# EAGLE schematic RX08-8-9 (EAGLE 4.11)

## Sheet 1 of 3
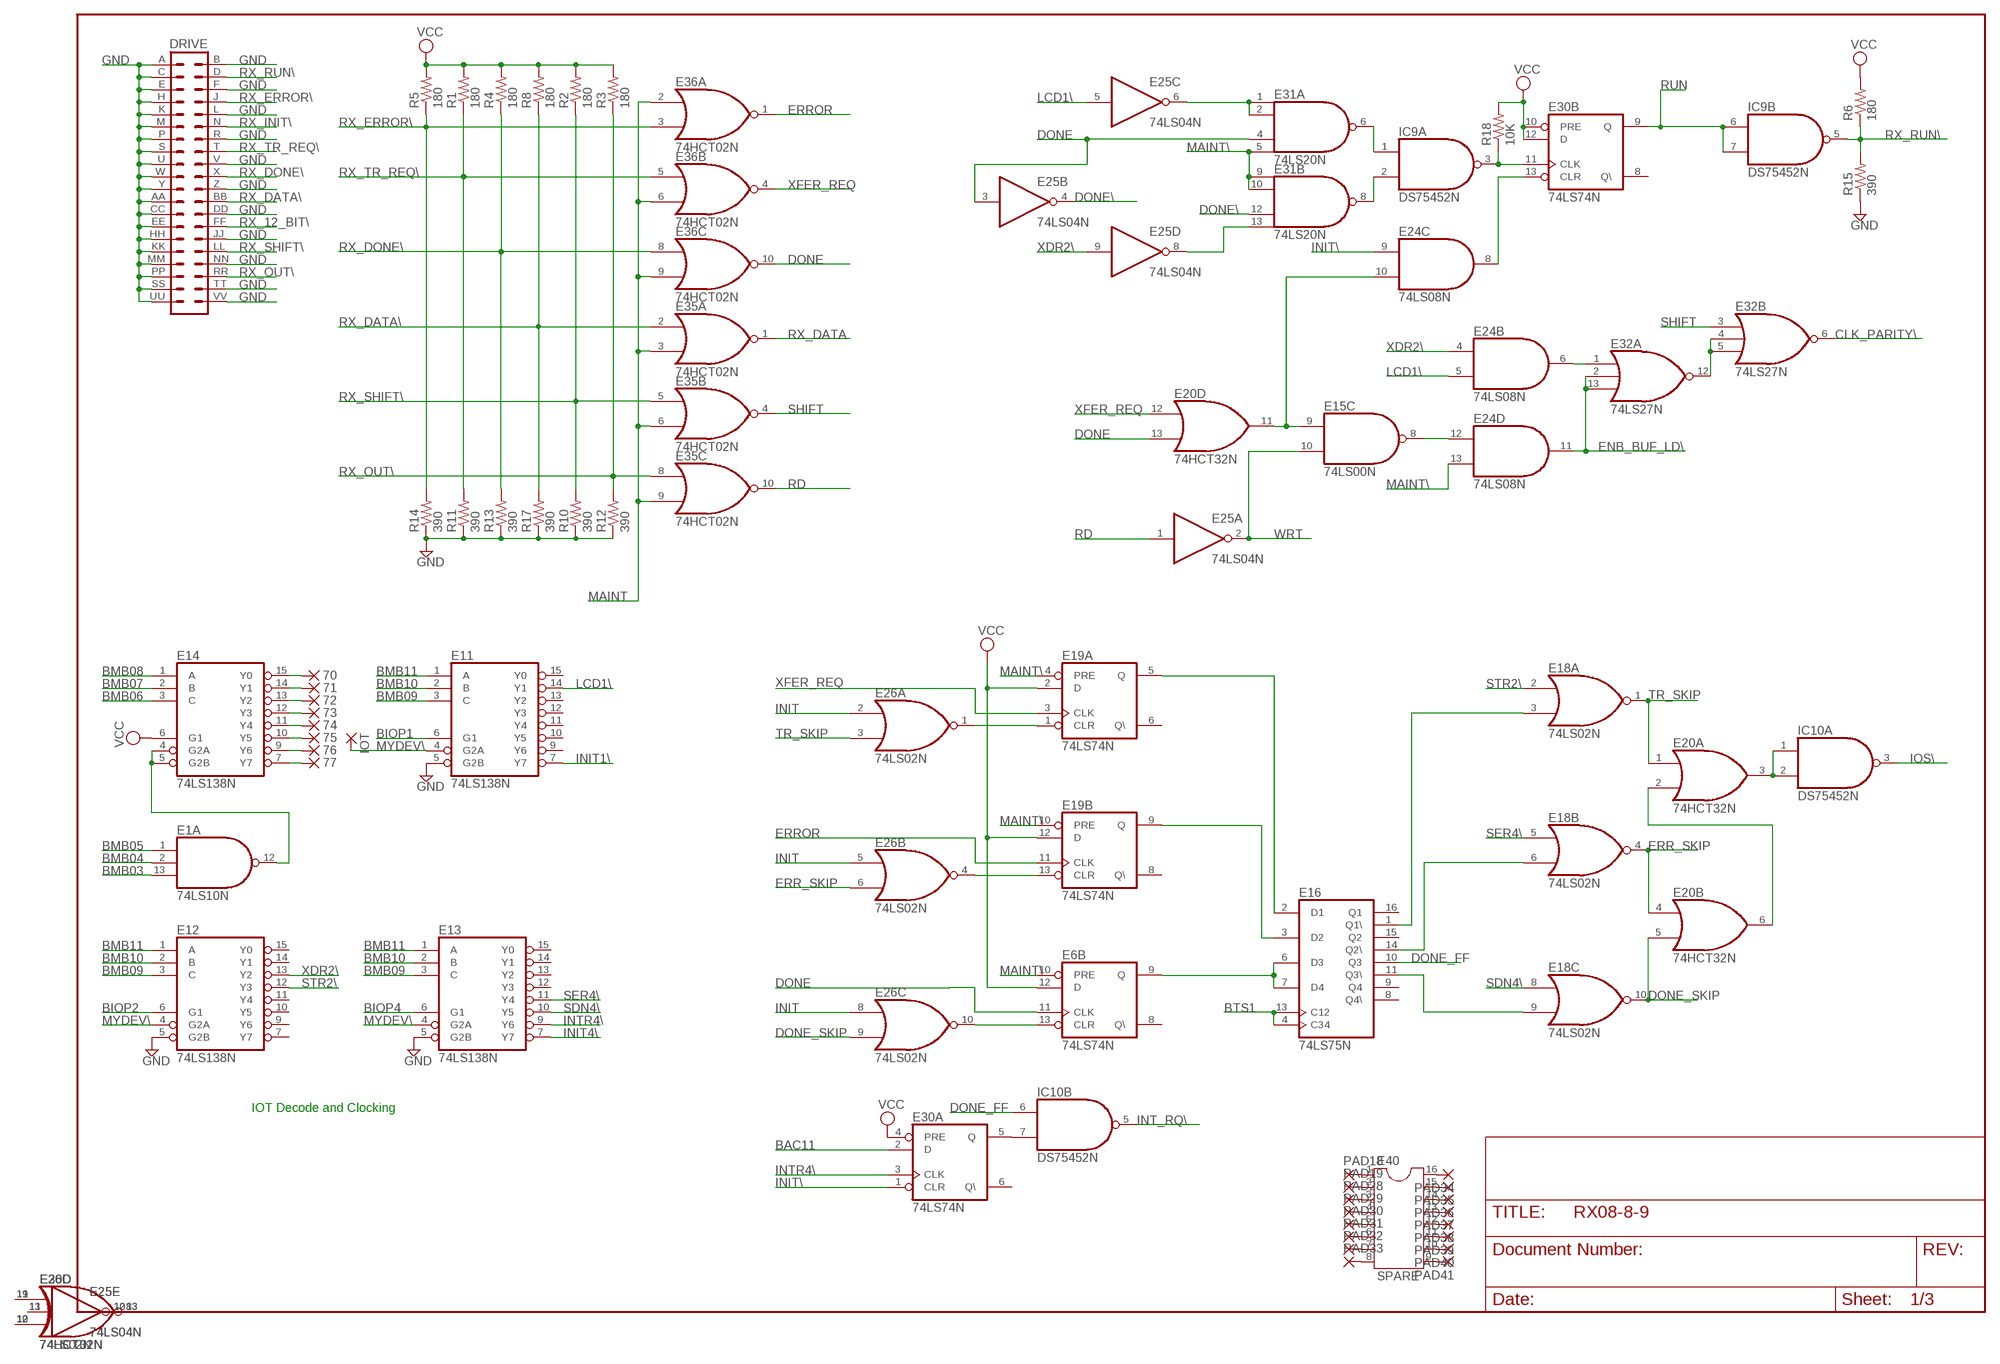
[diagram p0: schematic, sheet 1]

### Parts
70  1,6/0,8  [1,6/0,8]
71  1,6/0,8  [1,6/0,8]
72  1,6/0,8  [1,6/0,8]
73  1,6/0,8  [1,6/0,8]
74  1,6/0,8  [1,6/0,8]
75  1,6/0,8  [1,6/0,8]
76  1,6/0,8  [1,6/0,8]
77  1,6/0,8  [1,6/0,8]
DRIVE  DEC40PIN  [DEC40PIN]
E1  74LS10N  [DIL14]
E6  74LS74N  [DIL14]
E11  74LS138N  [DIL16]
E12  74LS138N  [DIL16]
E13  74LS138N  [DIL16]
E14  74LS138N  [DIL16]
E15  74LS00N  [DIL14]
E16  74LS75N  [DIL16]
E18  74LS02N  [DIL14]
E19  74LS74N  [DIL14]
E20  74HCT32N  [DIL14]
E24  74LS08N  [DIL14]
E25  74LS04N  [DIL14]
E26  74LS02N  [DIL14]
E30  74LS74N  [DIL14]
E31  74LS20N  [DIL14]
E32  74LS27N  [DIL14]
E35  74HCT02N  [DIL14]
E36  74HCT02N  [DIL14]
E40  SPARE  DIL16  [DIL16]
IC9  DS75452N  [DIL08]
IC10  DS75452N  [DIL08]
IOT  1,6/0,8  [1,6/0,8]
PAD18  1,6/0,8  [1,6/0,8]
PAD19  1,6/0,8  [1,6/0,8]
PAD28  1,6/0,8  [1,6/0,8]
PAD29  1,6/0,8  [1,6/0,8]
PAD30  1,6/0,8  [1,6/0,8]
PAD31  1,6/0,8  [1,6/0,8]
PAD32  1,6/0,8  [1,6/0,8]
PAD33  1,6/0,8  [1,6/0,8]
PAD34  1,6/0,8  [1,6/0,8]
PAD35  1,6/0,8  [1,6/0,8]
PAD36  1,6/0,8  [1,6/0,8]
PAD37  1,6/0,8  [1,6/0,8]
PAD38  1,6/0,8  [1,6/0,8]
PAD39  1,6/0,8  [1,6/0,8]
PAD40  1,6/0,8  [1,6/0,8]
PAD41  1,6/0,8  [1,6/0,8]
R1  180  R-US_0207/10  [0207/10]
R2  180  R-US_0207/10  [0207/10]
R3  180  R-US_0207/10  [0207/10]
R4  180  R-US_0207/10  [0207/10]
R5  180  R-US_0207/10  [0207/10]
R6  180  R-US_0207/10  [0207/10]
R8  180  R-US_0207/10  [0207/10]
R10  390  R-US_0207/10  [0207/10]
R11  390  R-US_0207/10  [0207/10]
R12  390  R-US_0207/10  [0207/10]
R13  390  R-US_0207/10  [0207/10]
R14  390  R-US_0207/10  [0207/10]
R15  390  R-US_0207/10  [0207/10]
R17  390  R-US_0207/10  [0207/10]
R18  10K  R-US_0207/10  [0207/10]

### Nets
BAC11: E30.2(A:D) ; also sheet 2,3
BIOP1: E11.6(G1) ; also sheet 3
BIOP2: E12.6(G1) ; also sheet 3
BIOP4: E13.6(G1) ; also sheet 3
BMB03: E1.13(A:I2) ; also sheet 3
BMB04: E1.2(A:I1) ; also sheet 3
BMB05: E1.1(A:I0) ; also sheet 3
BMB06: E14.3(C) ; also sheet 3
BMB07: E14.2(B) ; also sheet 3
BMB08: E14.1(A) ; also sheet 3
BMB09: E11.3(C) E12.3(C) E13.3(C) ; also sheet 3
BMB10: E11.2(B) E12.2(B) E13.2(B) ; also sheet 3
BMB11: E11.1(A) E12.1(A) E13.1(A) ; also sheet 3
BTS1: E16.4(C34) E16.13(C12) ; also sheet 3
CLK_PARITY\: E32.6(B:O) ; also sheet 2
DONE: E6.11(B:CLK) E20.13(D:I1) E25.3(B:I) E31.4(A:I2) E36.10(C:O) ; also sheet 2
DONE\: E25.4(B:O) E31.12(B:I2) ; also sheet 2
DONE_FF: E16.10(Q3) IC10.6(B:I0)
DONE_SKIP: E18.10(C:O) E20.5(B:I1) E26.9(C:I1)
ENB_BUF_LD\: E24.11(D:O) E32.2(A:I1) E32.13(A:I2) ; also sheet 2
ERR_SKIP: E18.4(B:O) E20.4(B:I0) E26.6(B:I1)
ERROR: E19.11(B:CLK) E36.1(A:O)
GND [supply]: DRIVE.A DRIVE.AA DRIVE.B DRIVE.C DRIVE.CC DRIVE.DD DRIVE.E DRIVE.EE DRIVE.F DRIVE.H DRIVE.HH DRIVE.JJ DRIVE.K DRIVE.KK DRIVE.L DRIVE.M DRIVE.MM DRIVE.NN DRIVE.P DRIVE.PP DRIVE.R DRIVE.S DRIVE.SS DRIVE.TT DRIVE.U DRIVE.UU DRIVE.V DRIVE.VV DRIVE.W DRIVE.Y DRIVE.Z E11.5(G2B) E12.5(G2B) E13.5(G2B) R10.1 R11.1 R12.1 R13.1 R14.1 R15.1 R17.1 ; also sheet 2,3
INIT: E26.2(A:I0) E26.5(B:I0) E26.8(C:I0) ; also sheet 2
INIT1\: E11.7(Y7) ; also sheet 2
INIT4\: E13.7(Y7) ; also sheet 2
INIT\: E24.9(C:I0) E30.1(A:CLR) ; also sheet 2
INT_RQ\: IC10.5(B:O) ; also sheet 3
INTR4\: E13.9(Y6) E30.3(A:CLK)
IOS\: IC10.3(A:O) ; also sheet 3
LCD1: E25.6(C:O) E31.1(A:I0) E31.2(A:I1)
LCD1\: E11.14(Y1) E24.5(B:I1) E25.5(C:I) ; also sheet 2
MAINT: E35.3(A:I1) E35.6(B:I1) E35.9(C:I1) E36.2(A:I0) E36.6(B:I1) E36.9(C:I1) ; also sheet 2
MAINT\: E6.10(B:PRE) E19.4(A:PRE) E19.10(B:PRE) E24.13(D:I1) E31.5(A:I3) E31.9(B:I0) E31.10(B:I1) ; also sheet 2
MYDEV\: E11.4(G2A) E12.4(G2A) E13.4(G2A) IOT.1(P)
N$1: 76.1(P) E14.9(Y6)
N$5: 70.1(P) E14.15(Y0)
N$6: 71.1(P) E14.14(Y1)
N$7: 72.1(P) E14.13(Y2)
N$8: 73.1(P) E14.12(Y3)
N$9: 74.1(P) E14.11(Y4)
N$10: 75.1(P) E14.10(Y5)
N$11: 77.1(P) E14.7(Y7)
N$22: E15.9(C:I0) E20.11(D:O) E24.10(C:I1)
N$32: E15.8(C:O) E24.12(D:I0)
N$34: E40.1 PAD18.1(P)
N$41: E40.2 PAD19.1(P)
N$43: E40.3 PAD28.1(P)
N$44: E24.6(B:O) E32.1(A:I0)
N$49: E1.12(A:O) E14.4(G2A) E14.5(G2B)
N$50: E40.4 PAD29.1(P)
N$51: E40.5 PAD30.1(P)
N$52: E40.6 PAD31.1(P)
N$53: E40.7 PAD32.1(P)
N$54: E40.8 PAD33.1(P)
N$55: E40.16 PAD34.1(P)
N$56: E40.15 PAD35.1(P)
N$57: E40.14 PAD36.1(P)
N$58: E40.13 PAD37.1(P)
N$59: E40.12 PAD38.1(P)
N$61: E40.11 PAD39.1(P)
N$68: E40.10 PAD40.1(P)
N$69: E40.9 PAD41.1(P)
N$86: E30.5(A:Q) IC10.7(B:I1)
N$87: E32.4(B:I1) E32.5(B:I2) E32.12(A:O)
N$88: E20.2(A:I1) E20.6(B:O)
N$89: E20.3(A:O) IC10.1(A:I0) IC10.2(A:I1)
N$92: E16.11(Q3\) E18.9(C:I1)
N$93: E16.14(Q2\) E18.6(B:I1)
N$94: E30.11(B:CLK) IC9.3(A:O) R18.1
N$95: E31.8(B:O) IC9.2(A:I1)
N$96: E16.1(Q1\) E18.3(A:I1)
N$98: E31.6(A:O) IC9.1(A:I0)
N$99: E24.8(C:O) E30.13(B:CLR)
N$100: E16.2(D1) E19.5(A:Q)
N$102: E25.8(D:O) E31.13(B:I3)
N$103: E16.3(D2) E19.9(B:Q)
N$107: E6.9(B:Q) E16.6(D3) E16.7(D4)
N$108: E19.1(A:CLR) E26.1(A:O)
N$110: E19.13(B:CLR) E26.4(B:O)
N$111: E6.13(B:CLR) E26.10(C:O)
RD: E25.1(A:I) E35.10(C:O) ; also sheet 2
RUN: E30.9(B:Q) IC9.6(B:I0) IC9.7(B:I1) ; also sheet 2
RX_12_BIT\: DRIVE.FF ; also sheet 2
RX_DATA: E35.1(A:O) ; also sheet 2
RX_DATA\: DRIVE.BB E35.2(A:I0) R8.1 R17.2 ; also sheet 2
RX_DONE\: DRIVE.X E36.8(C:I0) R4.1 R13.2
RX_ERROR\: DRIVE.J E36.3(A:I1) R5.1 R14.2
RX_INIT\: DRIVE.N ; also sheet 2
RX_OUT\: DRIVE.RR E35.8(C:I0) R3.1 R12.2
RX_RUN\: DRIVE.D IC9.5(B:O) R6.1 R15.2
RX_SHIFT\: DRIVE.LL E35.5(B:I0) R2.1 R10.2
RX_TR_REQ\: DRIVE.T E36.5(B:I0) R1.1 R11.2
SDN4\: E13.10(Y5) E18.8(C:I0)
SER4\: E13.11(Y4) E18.5(B:I0)
SHIFT: E32.3(B:I0) E35.4(B:O)
STR2\: E12.12(Y3) E18.2(A:I0)
TR_SKIP: E18.1(A:O) E20.1(A:I0) E26.3(A:I1)
VCC [supply]: E6.12(B:D) E14.6(G1) E19.2(A:D) E19.12(B:D) E30.4(A:PRE) E30.10(B:PRE) E30.12(B:D) R1.2 R2.2 R3.2 R4.2 R5.2 R6.2 R8.2 R18.2 ; also sheet 2,3
WRT: E15.10(C:I1) E25.2(A:O) ; also sheet 2
XDR2\: E12.13(Y2) E24.4(B:I0) E25.9(D:I) ; also sheet 2
XFER_REQ: E19.3(A:CLK) E20.12(D:I0) E36.4(B:O)
Unconnected: E11.9(Y6) E11.10(Y5) E11.11(Y4) E11.12(Y3) E11.13(Y2) E11.15(Y0) E12.7(Y7) E12.9(Y6) E12.10(Y5) E12.11(Y4) E12.14(Y1) E12.15(Y0) E13.12(Y3) E13.13(Y2) E13.14(Y1) E13.15(Y0) E16.8(Q4\) E16.9(Q4) E16.15(Q2) E16.16(Q1) E19.6(A:Q\) E19.8(B:Q\) E30.6(A:Q\) E30.8(B:Q\)

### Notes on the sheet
- IOT Decode and Clocking

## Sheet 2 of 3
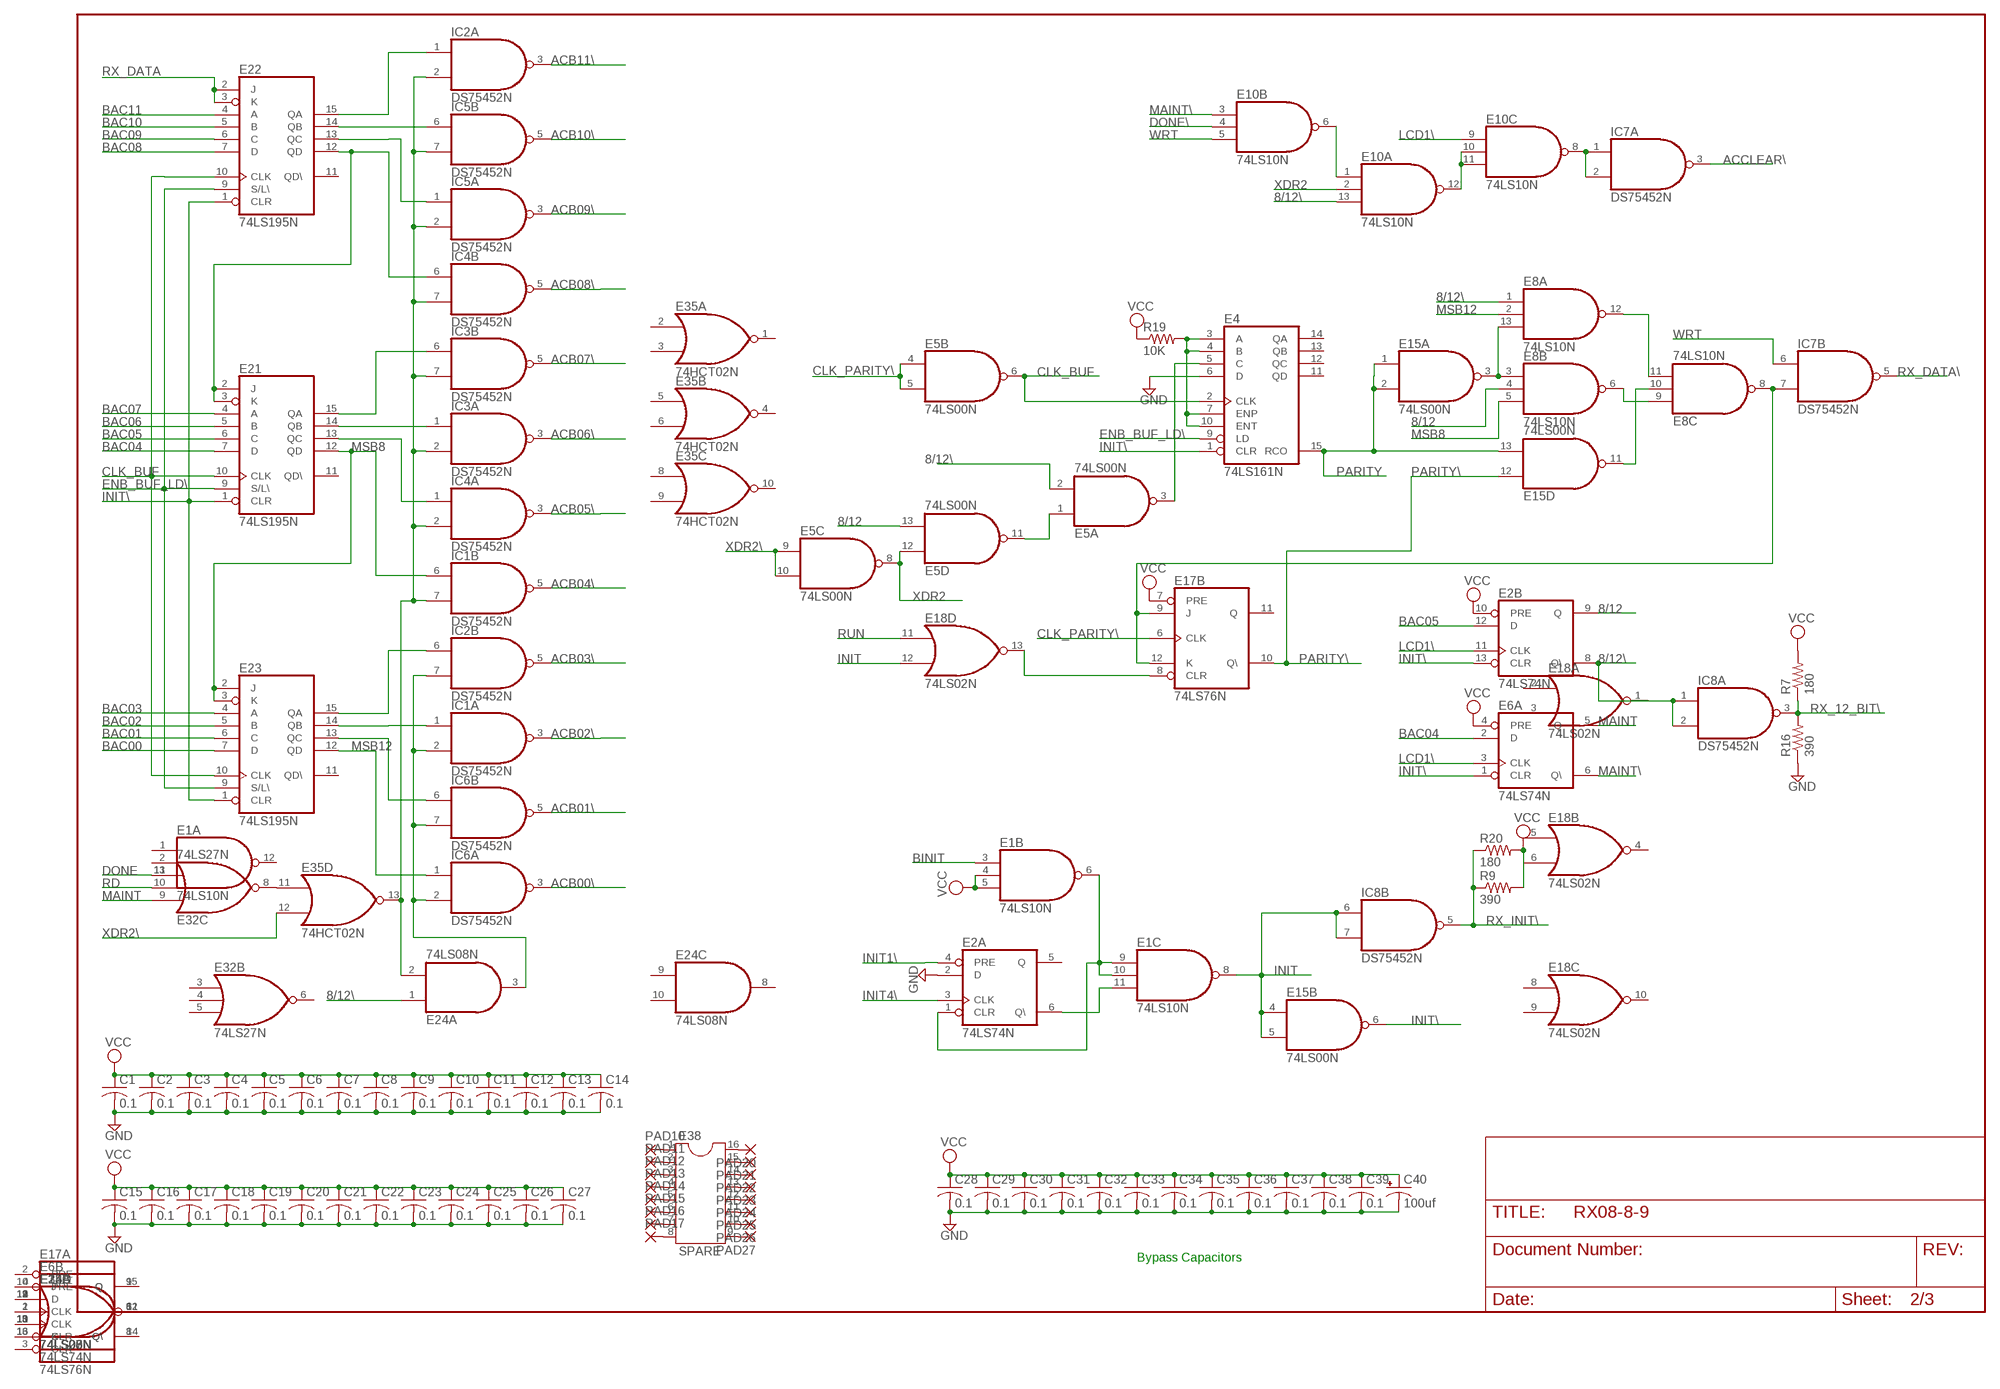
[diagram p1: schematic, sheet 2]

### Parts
C1  0.1  C-US050-025X075  [C050-025X075]
C2  0.1  C-US050-025X075  [C050-025X075]
C3  0.1  C-US050-025X075  [C050-025X075]
C4  0.1  C-US050-025X075  [C050-025X075]
C5  0.1  C-US050-025X075  [C050-025X075]
C6  0.1  C-US050-025X075  [C050-025X075]
C7  0.1  C-US050-025X075  [C050-025X075]
C8  0.1  C-US050-025X075  [C050-025X075]
C9  0.1  C-US050-025X075  [C050-025X075]
C10  0.1  C-US050-025X075  [C050-025X075]
C11  0.1  C-US050-025X075  [C050-025X075]
C12  0.1  C-US050-025X075  [C050-025X075]
C13  0.1  C-US050-025X075  [C050-025X075]
C14  0.1  C-US050-025X075  [C050-025X075]
C15  0.1  C-US050-025X075  [C050-025X075]
C16  0.1  C-US050-025X075  [C050-025X075]
C17  0.1  C-US050-025X075  [C050-025X075]
C18  0.1  C-US050-025X075  [C050-025X075]
C19  0.1  C-US050-025X075  [C050-025X075]
C20  0.1  C-US050-025X075  [C050-025X075]
C21  0.1  C-US050-025X075  [C050-025X075]
C22  0.1  C-US050-025X075  [C050-025X075]
C23  0.1  C-US050-025X075  [C050-025X075]
C24  0.1  C-US050-025X075  [C050-025X075]
C25  0.1  C-US050-025X075  [C050-025X075]
C26  0.1  C-US050-025X075  [C050-025X075]
C27  0.1  C-US050-025X075  [C050-025X075]
C28  0.1  C-US050-025X075  [C050-025X075]
C29  0.1  C-US050-025X075  [C050-025X075]
C30  0.1  C-US050-025X075  [C050-025X075]
C31  0.1  C-US050-025X075  [C050-025X075]
C32  0.1  C-US050-025X075  [C050-025X075]
C33  0.1  C-US050-025X075  [C050-025X075]
C34  0.1  C-US050-025X075  [C050-025X075]
C35  0.1  C-US050-025X075  [C050-025X075]
C36  0.1  C-US050-025X075  [C050-025X075]
C37  0.1  C-US050-025X075  [C050-025X075]
C38  0.1  C-US050-025X075  [C050-025X075]
C39  0.1  C-US050-025X075  [C050-025X075]
C40  100uf  CPOL-USE22-9AXIAL  [E22-9]
E2  74LS74N  [DIL14]
E4  74LS161N  [DIL16]
E5  74LS00N  [DIL14]
E8  74LS10N  [DIL14]
E10  74LS10N  [DIL14]
E17  74LS76N  [DIL16]
E21  74LS195N  [DIL16]
E22  74LS195N  [DIL16]
E23  74LS195N  [DIL16]
E38  SPARE  DIL16  [DIL16]
IC1  DS75452N  [DIL08]
IC2  DS75452N  [DIL08]
IC3  DS75452N  [DIL08]
IC4  DS75452N  [DIL08]
IC5  DS75452N  [DIL08]
IC6  DS75452N  [DIL08]
IC7  DS75452N  [DIL08]
IC8  DS75452N  [DIL08]
PAD10  1,6/0,8  [1,6/0,8]
PAD11  1,6/0,8  [1,6/0,8]
PAD12  1,6/0,8  [1,6/0,8]
PAD13  1,6/0,8  [1,6/0,8]
PAD14  1,6/0,8  [1,6/0,8]
PAD15  1,6/0,8  [1,6/0,8]
PAD16  1,6/0,8  [1,6/0,8]
PAD17  1,6/0,8  [1,6/0,8]
PAD20  1,6/0,8  [1,6/0,8]
PAD21  1,6/0,8  [1,6/0,8]
PAD22  1,6/0,8  [1,6/0,8]
PAD23  1,6/0,8  [1,6/0,8]
PAD24  1,6/0,8  [1,6/0,8]
PAD25  1,6/0,8  [1,6/0,8]
PAD26  1,6/0,8  [1,6/0,8]
PAD27  1,6/0,8  [1,6/0,8]
R7  180  R-US_0207/10  [0207/10]
R9  390  R-US_0207/10  [0207/10]
R16  390  R-US_0207/10  [0207/10]
R19  10K  R-US_0207/10  [0207/10]
R20  180  R-US_0207/10  [0207/10]

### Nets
8/12: E2.9(B:Q) E5.13(D:I1) E8.4(B:I1)
8/12\: E2.8(B:Q\) E5.2(A:I1) E8.1(A:I0) E10.13(A:I2) E24.1(A:I0) IC8.1(A:I0) IC8.2(A:I1)
ACB00\: IC6.3(A:O) ; also sheet 3
ACB01\: IC6.5(B:O) ; also sheet 3
ACB02\: IC1.3(A:O) ; also sheet 3
ACB03\: IC2.5(B:O) ; also sheet 3
ACB04\: IC1.5(B:O) ; also sheet 3
ACB05\: IC4.3(A:O) ; also sheet 3
ACB06\: IC3.3(A:O) ; also sheet 3
ACB07\: IC3.5(B:O) ; also sheet 3
ACB08\: IC4.5(B:O) ; also sheet 3
ACB09\: IC5.3(A:O) ; also sheet 3
ACB10\: IC5.5(B:O) ; also sheet 3
ACB11\: IC2.3(A:O) ; also sheet 3
ACCLEAR\: IC7.3(A:O) ; also sheet 3
BAC00: E23.7(D) ; also sheet 3
BAC01: E23.6(C) ; also sheet 3
BAC02: E23.5(B) ; also sheet 3
BAC03: E23.4(A) ; also sheet 3
BAC04: E6.2(A:D) E21.7(D) ; also sheet 3
BAC05: E2.12(B:D) E21.6(C) ; also sheet 3
BAC06: E21.5(B) ; also sheet 3
BAC07: E21.4(A) ; also sheet 3
BAC08: E22.7(D) ; also sheet 3
BAC09: E22.6(C) ; also sheet 3
BAC10: E22.5(B) ; also sheet 3
BAC11: E22.4(A) ; also sheet 1,3
BINIT: E1.3(B:I0) ; also sheet 3
CLK_BUF: E4.2(CLK) E5.6(B:O) E21.10(CLK) E22.10(CLK) E23.10(CLK)
CLK_PARITY\: E5.4(B:I0) E5.5(B:I1) E17.6(B:CLK) ; also sheet 1
DONE: E32.11(C:I2) ; also sheet 1
DONE\: E10.4(B:I1) ; also sheet 1
ENB_BUF_LD\: E4.9(LD) E21.9(S/L\) E22.9(S/L\) E23.9(S/L\) ; also sheet 1
GND [supply]: C1.2 C2.2 C3.2 C4.2 C5.2 C6.2 C7.2 C8.2 C9.2 C10.2 C11.2 C12.2 C13.2 C14.2 C15.2 C16.2 C17.2 C18.2 C19.2 C20.2 C21.2 C22.2 C23.2 C24.2 C25.2 C26.2 C27.2 C28.2 C29.2 C30.2 C31.2 C32.2 C33.2 C34.2 C35.2 C36.2 C37.2 C38.2 C39.2 C40.- E2.2(A:D) E4.6(D) R16.1 ; also sheet 1,3
INIT: E1.8(C:O) E15.4(B:I0) E15.5(B:I1) E18.12(D:I1) IC8.6(B:I0) IC8.7(B:I1) ; also sheet 1
INIT1\: E2.4(A:PRE) ; also sheet 1
INIT4\: E2.3(A:CLK) ; also sheet 1
INIT\: E2.13(B:CLR) E4.1(CLR) E6.1(A:CLR) E15.6(B:O) E21.1(CLR) E22.1(CLR) E23.1(CLR) ; also sheet 1
LCD1\: E2.11(B:CLK) E6.3(A:CLK) E10.9(C:I0) ; also sheet 1
MAINT: E6.5(A:Q) E32.9(C:I0) ; also sheet 1
MAINT\: E6.6(A:Q\) E10.3(B:I0) ; also sheet 1
MSB8: E8.5(B:I2) E21.12(QD) E23.2(J) E23.3(K) IC1.6(B:I0)
MSB12: E8.2(A:I1) E23.12(QD) IC6.1(A:I0)
N$2: E23.14(QB) IC1.1(A:I0)
N$3: E24.2(A:I1) E35.13(D:O) IC1.7(B:I1) IC2.2(A:I1) IC3.2(A:I1) IC3.7(B:I1) IC4.2(A:I1) IC4.7(B:I1) IC5.2(A:I1) IC5.7(B:I1)
N$4: E32.8(C:O) E35.11(D:I0)
N$12: E24.3(A:O) IC1.2(A:I1) IC2.7(B:I1) IC6.2(A:I1) IC6.7(B:I1)
N$13: E38.1 PAD10.1(P)
N$14: E38.2 PAD11.1(P)
N$15: E38.3 PAD12.1(P)
N$16: E38.4 PAD13.1(P)
N$17: E38.5 PAD14.1(P)
N$18: E38.6 PAD15.1(P)
N$19: E38.7 PAD16.1(P)
N$20: E38.8 PAD17.1(P)
N$21: E4.5(C) E5.3(A:O)
N$23: E38.16 PAD20.1(P)
N$24: E38.15 PAD21.1(P)
N$25: E38.14 PAD22.1(P)
N$26: E38.13 PAD23.1(P)
N$27: E38.12 PAD24.1(P)
N$28: E38.11 PAD25.1(P)
N$29: E38.10 PAD26.1(P)
N$30: E38.9 PAD27.1(P)
N$31: E21.2(J) E21.3(K) E22.12(QD) IC4.6(B:I0)
N$33: E23.13(QC) IC6.6(B:I0)
N$35: E5.1(A:I0) E5.11(D:O)
N$36: E1.6(B:O) E1.9(C:I0) E1.10(C:I1) E2.1(A:CLR)
N$37: E8.3(B:I0) E8.13(A:I2) E15.3(A:O)
N$38: E8.11(C:I2) E8.12(A:O)
N$39: E8.6(B:O) E8.9(C:I0)
N$40: E8.10(C:I1) E15.11(D:O)
N$42: E8.8(C:O) E17.9(B:J) E17.12(B:K) IC7.7(B:I1)
N$45: E1.11(C:I2) E2.6(A:Q\)
N$46: E17.8(B:CLR) E18.13(D:O)
N$48: E4.3(A) E4.4(B) E4.7(ENP) E4.10(ENT) R19.2
N$60: E23.15(QA) IC2.6(B:I0)
N$62: E21.13(QC) IC4.1(A:I0)
N$63: E21.14(QB) IC3.1(A:I0)
N$64: E21.15(QA) IC3.6(B:I0)
N$65: E22.15(QA) IC2.1(A:I0)
N$66: E22.13(QC) IC5.1(A:I0)
N$67: E22.14(QB) IC5.6(B:I0)
N$104: E10.1(A:I0) E10.6(B:O)
N$105: E10.10(C:I1) E10.11(C:I2) E10.12(A:O)
N$106: E10.8(C:O) IC7.1(A:I0) IC7.2(A:I1)
PARITY: E4.15(RCO) E15.1(A:I0) E15.2(A:I1) E15.13(D:I1)
PARITY\: E15.12(D:I0) E17.10(B:Q\)
RD: E32.10(C:I1) ; also sheet 1
RUN: E18.11(D:I0) ; also sheet 1
RX_12_BIT\: IC8.3(A:O) R7.1 R16.2 ; also sheet 1
RX_DATA: E22.2(J) E22.3(K) ; also sheet 1
RX_DATA\: IC7.5(B:O) ; also sheet 1
RX_INIT\: IC8.5(B:O) R9.1 R20.1 ; also sheet 1
VCC [supply]: C1.1 C2.1 C3.1 C4.1 C5.1 C6.1 C7.1 C8.1 C9.1 C10.1 C11.1 C12.1 C13.1 C14.1 C15.1 C16.1 C17.1 C18.1 C19.1 C20.1 C21.1 C22.1 C23.1 C24.1 C25.1 C26.1 C27.1 C28.1 C29.1 C30.1 C31.1 C32.1 C33.1 C34.1 C35.1 C36.1 C37.1 C38.1 C39.1 C40.+ E1.4(B:I1) E1.5(B:I2) E2.10(B:PRE) E6.4(A:PRE) E17.7(B:PRE) R7.2 R9.2 R19.1 R20.2 ; also sheet 1,3
WRT: E10.5(B:I2) IC7.6(B:I0) ; also sheet 1
XDR2: E5.8(C:O) E5.12(D:I0) E10.2(A:I1)
XDR2\: E5.9(C:I0) E5.10(C:I1) E35.12(D:I1) ; also sheet 1
Unconnected: E2.5(A:Q) E4.11(QD) E4.12(QC) E4.13(QB) E4.14(QA) E6.8(B:Q\) E17.11(B:Q) E21.11(QD\) E22.11(QD\) E23.11(QD\)

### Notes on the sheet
- Bypass Capacitors

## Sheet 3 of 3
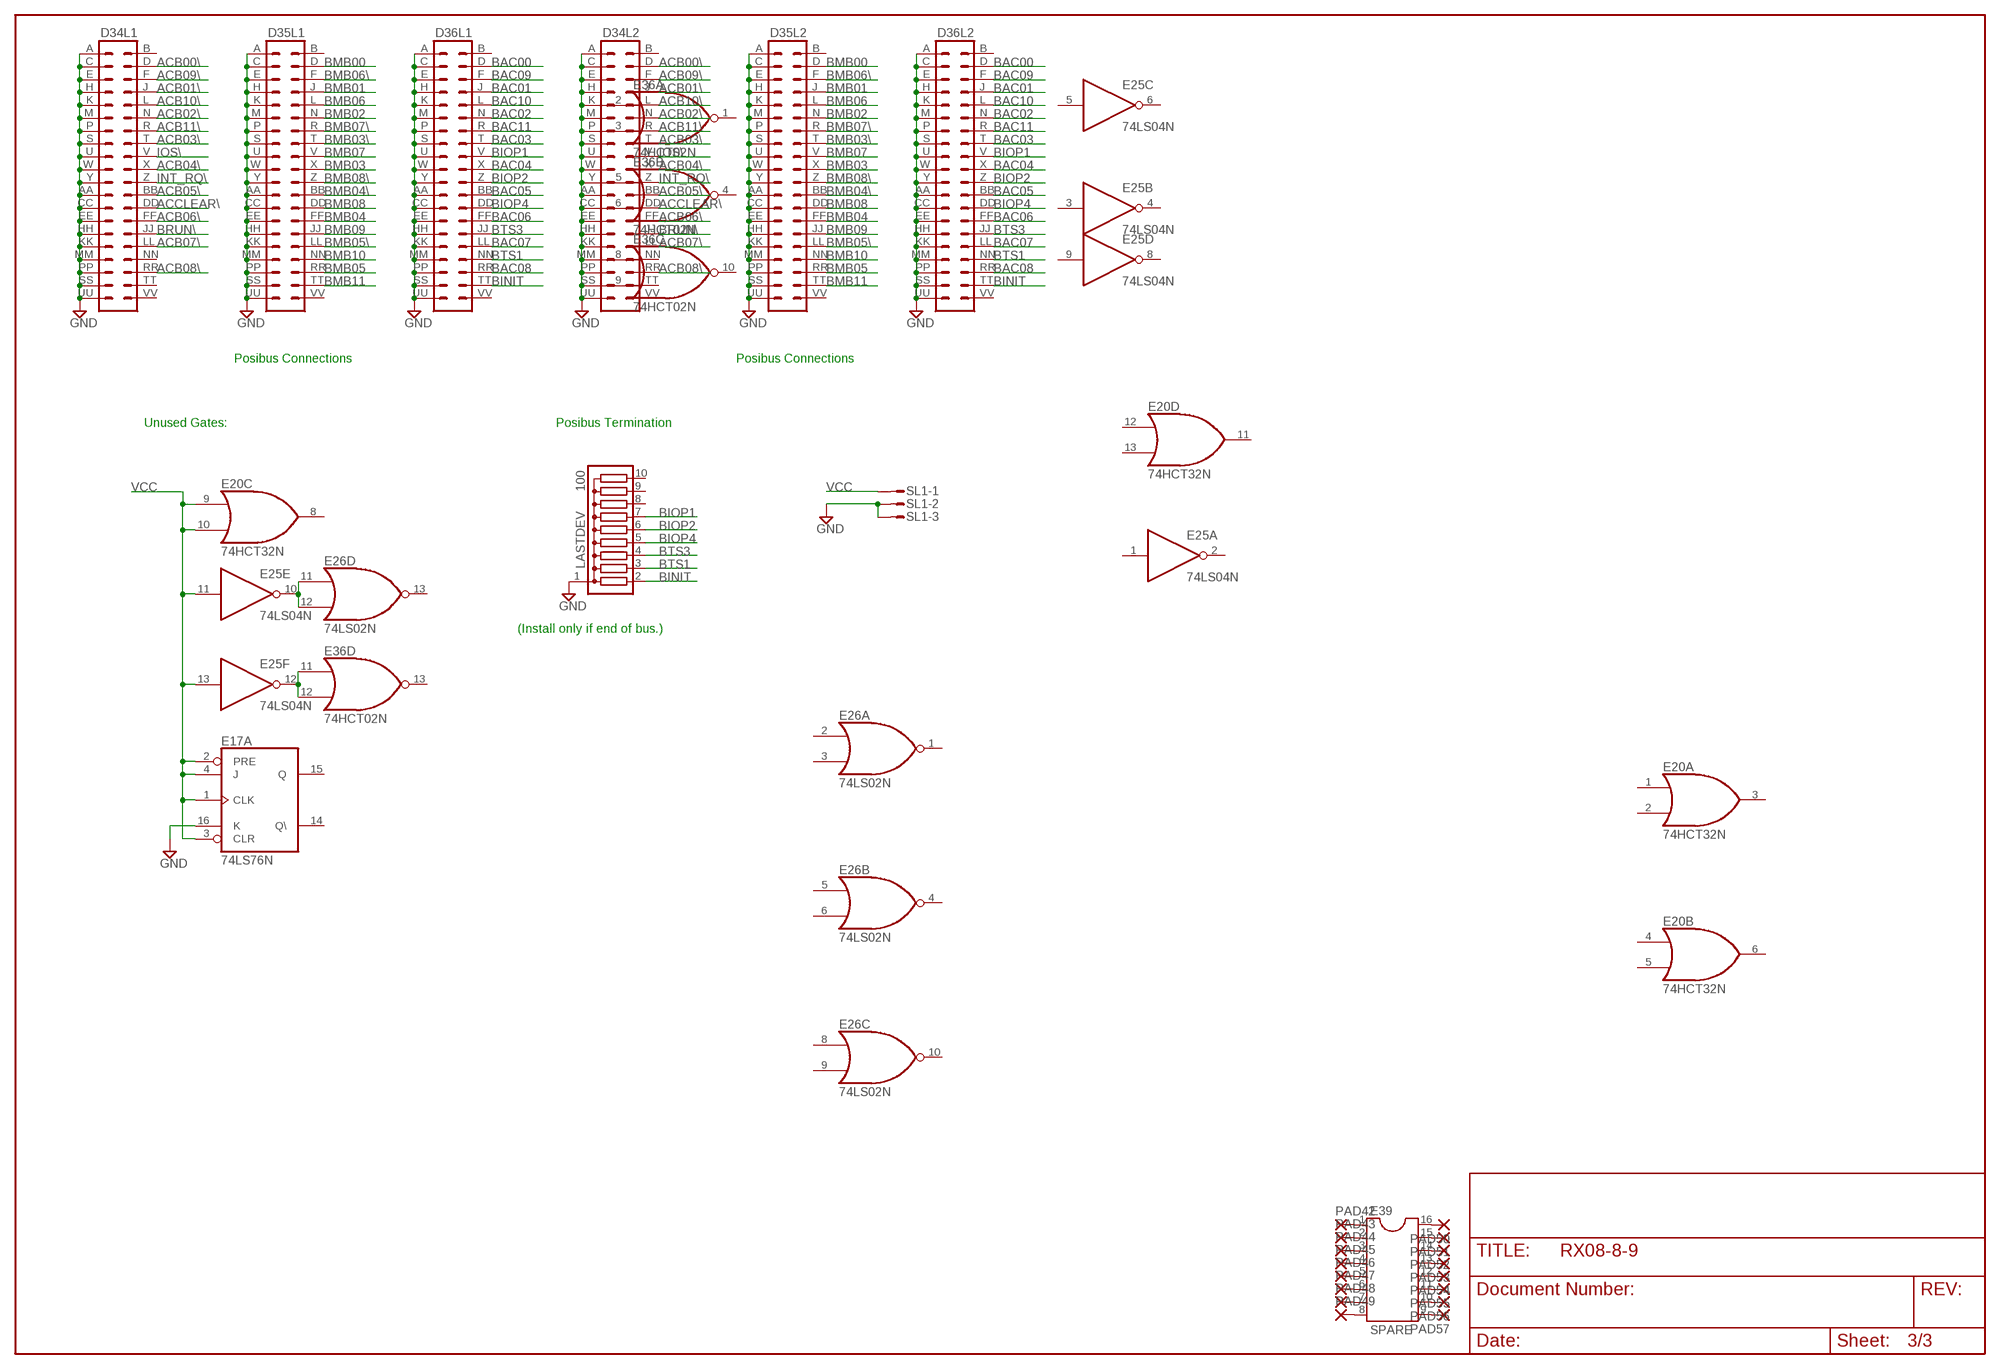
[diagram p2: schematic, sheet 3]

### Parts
D34L1  DEC40PIN  [DEC40PIN]
D34L2  DEC40PIN  [DEC40PIN]
D35L1  DEC40PIN  [DEC40PIN]
D35L2  DEC40PIN  [DEC40PIN]
D36L1  DEC40PIN  [DEC40PIN]
D36L2  DEC40PIN  [DEC40PIN]
E39  SPARE  DIL16  [DIL16]
LASTDEV  100  G09R  [SIL10]
PAD42  1,6/0,8  [1,6/0,8]
PAD43  1,6/0,8  [1,6/0,8]
PAD44  1,6/0,8  [1,6/0,8]
PAD45  1,6/0,8  [1,6/0,8]
PAD46  1,6/0,8  [1,6/0,8]
PAD47  1,6/0,8  [1,6/0,8]
PAD48  1,6/0,8  [1,6/0,8]
PAD49  1,6/0,8  [1,6/0,8]
PAD50  1,6/0,8  [1,6/0,8]
PAD51  1,6/0,8  [1,6/0,8]
PAD52  1,6/0,8  [1,6/0,8]
PAD53  1,6/0,8  [1,6/0,8]
PAD54  1,6/0,8  [1,6/0,8]
PAD55  1,6/0,8  [1,6/0,8]
PAD56  1,6/0,8  [1,6/0,8]
PAD57  1,6/0,8  [1,6/0,8]
SL1  MA04S  [04PA]

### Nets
ACB00\: D34L1.D D34L2.D ; also sheet 2
ACB01\: D34L1.J D34L2.J ; also sheet 2
ACB02\: D34L1.N D34L2.N ; also sheet 2
ACB03\: D34L1.T D34L2.T ; also sheet 2
ACB04\: D34L1.X D34L2.X ; also sheet 2
ACB05\: D34L1.BB D34L2.BB ; also sheet 2
ACB06\: D34L1.FF D34L2.FF ; also sheet 2
ACB07\: D34L1.LL D34L2.LL ; also sheet 2
ACB08\: D34L1.RR D34L2.RR ; also sheet 2
ACB09\: D34L1.F D34L2.F ; also sheet 2
ACB10\: D34L1.L D34L2.L ; also sheet 2
ACB11\: D34L1.R D34L2.R ; also sheet 2
ACCLEAR\: D34L1.DD D34L2.DD ; also sheet 2
BAC00: D36L1.D D36L2.D ; also sheet 2
BAC01: D36L1.J D36L2.J ; also sheet 2
BAC02: D36L1.N D36L2.N ; also sheet 2
BAC03: D36L1.T D36L2.T ; also sheet 2
BAC04: D36L1.X D36L2.X ; also sheet 2
BAC05: D36L1.BB D36L2.BB ; also sheet 2
BAC06: D36L1.FF D36L2.FF ; also sheet 2
BAC07: D36L1.LL D36L2.LL ; also sheet 2
BAC08: D36L1.RR D36L2.RR ; also sheet 2
BAC09: D36L1.F D36L2.F ; also sheet 2
BAC10: D36L1.L D36L2.L ; also sheet 2
BAC11: D36L1.R D36L2.R ; also sheet 1,2
BINIT: D36L1.TT D36L2.TT LASTDEV.2 ; also sheet 2
BIOP1: D36L1.V D36L2.V LASTDEV.7 ; also sheet 1
BIOP2: D36L1.Z D36L2.Z LASTDEV.6 ; also sheet 1
BIOP4: D36L1.DD D36L2.DD LASTDEV.5 ; also sheet 1
BMB00: D35L1.D D35L2.D
BMB01: D35L1.J D35L2.J
BMB02: D35L1.N D35L2.N
BMB03: D35L1.X D35L2.X ; also sheet 1
BMB03\: D35L1.T D35L2.T
BMB04: D35L1.FF D35L2.FF ; also sheet 1
BMB04\: D35L1.BB D35L2.BB
BMB05: D35L1.RR D35L2.RR ; also sheet 1
BMB05\: D35L1.LL D35L2.LL
BMB06: D35L1.L D35L2.L ; also sheet 1
BMB06\: D35L1.F D35L2.F
BMB07: D35L1.V D35L2.V ; also sheet 1
BMB07\: D35L1.R D35L2.R
BMB08: D35L1.DD D35L2.DD ; also sheet 1
BMB08\: D35L1.Z D35L2.Z
BMB09: D35L1.JJ D35L2.JJ ; also sheet 1
BMB10: D35L1.NN D35L2.NN ; also sheet 1
BMB11: D35L1.TT D35L2.TT ; also sheet 1
BRUN\: D34L1.JJ D34L2.JJ
BTS1: D36L1.NN D36L2.NN LASTDEV.3 ; also sheet 1
BTS3: D36L1.JJ D36L2.JJ LASTDEV.4
GND [supply]: D34L1.A D34L1.AA D34L1.C D34L1.CC D34L1.E D34L1.EE D34L1.H D34L1.HH D34L1.K D34L1.KK D34L1.M D34L1.MM D34L1.P D34L1.PP D34L1.S D34L1.SS D34L1.U D34L1.UU D34L1.W D34L1.Y D34L2.A D34L2.AA D34L2.C D34L2.CC D34L2.E D34L2.EE D34L2.H D34L2.HH D34L2.K D34L2.KK D34L2.M D34L2.MM D34L2.P D34L2.PP D34L2.S D34L2.SS D34L2.U D34L2.UU D34L2.W D34L2.Y D35L1.A D35L1.AA D35L1.C D35L1.CC D35L1.E D35L1.EE D35L1.H D35L1.HH D35L1.K D35L1.KK D35L1.M D35L1.MM D35L1.P D35L1.PP D35L1.S D35L1.SS D35L1.U D35L1.UU D35L1.W D35L1.Y D35L2.A D35L2.AA D35L2.C D35L2.CC D35L2.E D35L2.EE D35L2.H D35L2.HH D35L2.K D35L2.KK D35L2.M D35L2.MM D35L2.P D35L2.PP D35L2.S D35L2.SS D35L2.U D35L2.UU D35L2.W D35L2.Y D36L1.A D36L1.AA D36L1.C D36L1.CC D36L1.E D36L1.EE D36L1.H D36L1.HH D36L1.K D36L1.KK D36L1.M D36L1.MM D36L1.P D36L1.PP D36L1.S D36L1.SS D36L1.U D36L1.UU D36L1.W D36L1.Y D36L2.A D36L2.AA D36L2.C D36L2.CC D36L2.E D36L2.EE D36L2.H D36L2.HH D36L2.K D36L2.KK D36L2.M D36L2.MM D36L2.P D36L2.PP D36L2.S D36L2.SS D36L2.U D36L2.UU D36L2.W D36L2.Y E17.16(A:K) LASTDEV.1 SL1.2 SL1.3 ; also sheet 1,2
INT_RQ\: D34L1.Z D34L2.Z ; also sheet 1
IOS\: D34L1.V D34L2.V ; also sheet 1
N$47: E25.10(E:O) E26.11(D:I0) E26.12(D:I1)
N$70: E39.1 PAD42.1(P)
N$71: E39.2 PAD43.1(P)
N$72: E39.3 PAD44.1(P)
N$73: E39.4 PAD45.1(P)
N$74: E39.5 PAD46.1(P)
N$75: E39.6 PAD47.1(P)
N$76: E39.7 PAD48.1(P)
N$77: E39.8 PAD49.1(P)
N$78: E39.16 PAD50.1(P)
N$79: E39.15 PAD51.1(P)
N$80: E39.14 PAD52.1(P)
N$81: E39.13 PAD53.1(P)
N$82: E39.12 PAD54.1(P)
N$83: E39.11 PAD55.1(P)
N$84: E39.10 PAD56.1(P)
N$85: E39.9 PAD57.1(P)
N$101: E25.12(F:O) E36.11(D:I0) E36.12(D:I1)
VCC [supply]: E17.1(A:CLK) E17.2(A:PRE) E17.3(A:CLR) E17.4(A:J) E20.9(C:I0) E20.10(C:I1) E25.11(E:I) E25.13(F:I) SL1.1 ; also sheet 1,2
Unconnected: D34L1.B D34L1.NN D34L1.TT D34L1.VV D34L2.B D34L2.NN D34L2.TT D34L2.VV D35L1.B D35L1.VV D35L2.B D35L2.VV D36L1.B D36L1.VV D36L2.B D36L2.VV E17.14(A:Q\) E17.15(A:Q) E20.8(C:O) E26.13(D:O) E36.13(D:O) LASTDEV.8 LASTDEV.9 LASTDEV.10 SL1.4

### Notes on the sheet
- Posibus Connections | Posibus Connections
- Unused Gates: | Posibus Termination
- (Install only if end of bus.)

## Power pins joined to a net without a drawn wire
GND: E1.7(P:GND) E2.7(P:GND) E4.8(GND) E5.7(P:GND) E6.7(P:GND) E8.7(P:GND) E10.7(P:GND) E11.8(GND) E12.8(GND) E13.8(GND) E14.8(GND) E15.7(P:GND) E16.12(GND) E17.13(P:GND) E18.7(P:GND) E19.7(P:GND) E20.7(P:GND) E21.8(GND) E22.8(GND) E23.8(GND) E24.7(P:GND) E25.7(P:GND) E26.7(P:GND) E30.7(P:GND) E31.7(P:GND) E32.7(P:GND) E35.7(P:GND) E36.7(P:GND) IC1.4(P:GND) IC2.4(P:GND) IC3.4(P:GND) IC4.4(P:GND) IC5.4(P:GND) IC6.4(P:GND) IC7.4(P:GND) IC8.4(P:GND) IC9.4(P:GND) IC10.4(P:GND)
VCC: E1.14(P:VCC) E2.14(P:VCC) E4.16(VCC) E5.14(P:VCC) E6.14(P:VCC) E8.14(P:VCC) E10.14(P:VCC) E11.16(VCC) E12.16(VCC) E13.16(VCC) E14.16(VCC) E15.14(P:VCC) E16.5(VCC) E17.5(P:VCC) E18.14(P:VCC) E19.14(P:VCC) E20.14(P:VCC) E21.16(VCC) E22.16(VCC) E23.16(VCC) E24.14(P:VCC) E25.14(P:VCC) E26.14(P:VCC) E30.14(P:VCC) E31.14(P:VCC) E32.14(P:VCC) E35.14(P:VCC) E36.14(P:VCC) IC1.8(P:VCC) IC2.8(P:VCC) IC3.8(P:VCC) IC4.8(P:VCC) IC5.8(P:VCC) IC6.8(P:VCC) IC7.8(P:VCC) IC8.8(P:VCC) IC9.8(P:VCC) IC10.8(P:VCC)

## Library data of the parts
70-77 IOT PAD10-PAD57 = wirepad:1,6/0,8: THROUGH-HOLE PAD
C1-C39 = rcl:C-US: CAPACITOR, American symbol
C40 = rcl:CPOL-US: POLARIZED CAPACITOR, American symbol
D34L1 D34L2 D35L1 D35L2 D36L1 D36L2 DRIVE = dec-con:DEC40PIN: PIN HEADER
E1 E10 = 74xx-jameco:74*10: Triple 3-input NAND gate
E2 E6 E19 = 74xx-us:74*74: Dual D type positive edge triggered FLIP FLOP, preset and clear
E4 = 74xx-jameco:74*161: Synchronous 4-bit COUNTER
E5 E15 = 74xx-us:74*00: Quad 2-input NAND gate
E8 = 74xx-us:74*10: Triple 3-input NAND gate
E11-E14 = 74xx-jameco:74*138: 3-line to 8-line DECODER/DEMULTIPLEXER
E16 = 74xx-us:74*75: 4-bit bistable LATCH
E17 = 74xx-jameco:74*76: Dual J-K FLIP FLOP, preset and clear
E18 E35 E36 = 74xx-jameco:74*02: Quad 2-input NOR gate
E20 = 74xx-jameco:74*32: Quad 2-input OR gate
E21-E23 = 74xx-jameco:74*195: 4-bit parallel access SHIFT REGISTER
E24 = 74xx-us:74*08: Quad 2-input AND gate
E25 = 74xx-us:74*04: Hex INVERTER
E26 = 74xx-us:74*02: Quad 2-input NOR gate
E30 = 74xx-jameco:74*74: Dual D type positive edge triggered FLIP FLOP, preset and clear
E31 = 74xx-jameco:74*20: Dual 4-input NAND gate
E32 = 74xx-us:74*27: Triple 3-input NOR gate
E38-E40 = ic-package:DIL16: Dual In Line
IC1-IC10 = 74xx-jameco:DS75452: Quad 2-input NAND gate, open collector output
LASTDEV = resistor-sil:G09R: SIL RESISTOR
R1-R20 = rcl:R-US_: RESISTOR, American symbol
SL1 = con-amp-quick:MA04S: AMP QUICK CONNECTOR

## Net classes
1 supply: width 0.508 mm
